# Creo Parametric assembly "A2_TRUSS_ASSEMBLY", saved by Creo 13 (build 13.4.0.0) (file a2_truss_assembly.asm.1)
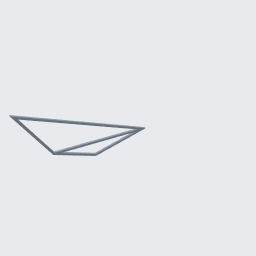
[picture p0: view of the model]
Units: millimeter Newton Second (mmNs); MM, TONNE, SECS

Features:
  1. datum plane "ASM_RIGHT"
  2. datum plane "ASM_TOP"
  3. datum plane "ASM_FRONT"
  4. coordinate system
  5. component "A2_TRUSS"
  6. component "PIN"
  7. component "PIN"
  8. component "PIN"
  9. component "PIN"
